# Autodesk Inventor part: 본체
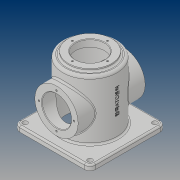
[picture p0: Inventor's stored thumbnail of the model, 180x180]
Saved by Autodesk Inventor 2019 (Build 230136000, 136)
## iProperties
Created: 2019-03
Part Number: 본체
Material: 일반
Document SubType Name: Modeling
Designer: PC312-19
Density: 1 g/cm^3
Appearance: 기본값
Author: PC312-19
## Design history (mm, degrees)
sketch "스케치1"
  geometry: C1 r 50 at (0, 0); 1 further point
  constraints: 1 centre point, 1 coincident
  dimensions: "d0" = 100 diameter of C1
extrude "돌출1" new body sketch "스케치1" stored distance "d1" = 120; taper "d2" = 0 deg
sketch "스케치2"
  geometry: C1 r 45 at (0, 0); 1 further point
  constraints: 1 centre point, 1 coincident
  dimensions: "d3" = 90 diameter of C1
extrude "돌출2" cut sketch "스케치2" distance "d4" = 112; taper "d5" = 0 deg
sketch "스케치3"
  geometry: C1 r 40 at (0, 0); 1 further point
  constraints: 1 centre point, 1 coincident
  dimensions: "d6" = 80 diameter of C1
extrude "돌출3" join sketch "스케치3" distance "d7" = 5; taper "d8" = 0 deg
sketch "스케치4"
  geometry: C1 r 27 at (0, 0); 1 further point
  constraints: 1 centre point, 1 coincident
  dimensions: "d9" = 54 diameter of C1
extrude "돌출4" cut sketch "스케치4" distance "d10" = 13; taper "d11" = 0 deg
node "작업 평면1"
sketch "스케치6"
  geometry: C1 r 40 at (0, 0); 1 further point
  constraints: 1 centre point, 1 coincident
  dimensions: "d13" = 80 diameter of C1
extrude "돌출5" join sketch "스케치6" stored distance "d14" = 13; taper "d15" = 0 deg
sketch "스케치7"
  geometry: 2 further points
  constraints: 1 vertical alignment
  dimensions: "d16" = 32.5 distance of point (0, 0) point (0, 32.5)
hole "구멍1" sketch "스케치7" at (0, 32.5) diameter "d17" = 3.242; stored, may be unused: countersink angle "d21" = 90 deg, drill point angle "d23" = 118 deg; dims "d18" = 8, "d19" = 4, "d20" = 2, "d22" = 10
sketch "스케치8"
  geometry: C1 r 27 at (0, 0); 1 further point
  constraints: 1 centre point, 1 coincident
  dimensions: "d27" = 54 diameter of C1
extrude "돌출6" cut sketch "스케치8" extent not by distance; stored distance "d28" = 13; taper "d29" = 0 deg
sketch "스케치9"
  geometry: L1 (70, 70)-(-70, 70); L2 (-70, 70)-(-70, -70); L3 (-70, -70)-(70, -70); L4 (70, -70)-(70, 70); L5 (70, 70)-(-70, -70); L6 (-70, 70)-(70, -70); C1 r 50 at (0, 0) reference; C2 r 45 at (0, 0) reference; 1 further point
  constraints: 12 end point, 2 midpoint, 2 parallel, 1 horizontal, 1 perpendicular
  dimensions: "d30" = 140 distance of L3.end L2.end; "d31" = 140 distance of L2.end L1.end
extrude "돌출7" join sketch "스케치9" distance "d32" = 10; taper "d33" = 0 deg
fillet "모깎기1" dims "d34" = 10
sketch "스케치10"
  geometry: C1 r 4.5 at (60, -60); C2 r 4.5 at (-60, -60); C3 r 4.5 at (-60, 60); C4 r 4.5 at (60, 60); 13 further points
  constraints: 4 centre point, 4 coincident, 4 other
  dimensions: "d35" = 9 diameter of C1; "d36" = 9 diameter of C2; "d37" = 9 diameter of C3; "d38" = 9 diameter of C4
extrude "돌출8" cut sketch "스케치10" extent not by distance; stored distance "d39" = 10; taper "d40" = 0 deg
node "작업 평면2"
sketch "스케치11"
  geometry: L1 (-50, 60)-(-50, -60) reference; L2 (-60, -60)-(-60, 60) reference; 2 further points
  constraints: 1 horizontal alignment, 1 other
  dimensions: "d65" = 70 distance from line of L2 point (10, 0)
feature "엠보싱1" sketch "스케치11" dims "d12" = 62, "d43" = 0.5, "d44" = 0
fillet "모깎기2" dims "d45" = 3
fillet "모깎기3" dims "d46" = 5
fillet "모깎기4" dims "d47" = 3
chamfer "모따기1" distance "d48" = 1; stored, may be unused: second distance "d49" = 2, angle "d50" = 45 deg
sketch "스케치12"
  geometry: 2 further points
  constraints: 1 vertical alignment
  dimensions: "d52" = 32.5 distance of point (0, 0) point (0, 32.5)
hole "구멍2" sketch "스케치12" at (0, 32.5) diameter "d53" = 3.242; stored, may be unused: countersink angle "d57" = 90 deg, drill point angle "d59" = 118 deg; dims "d54" = 8, "d55" = 4, "d56" = 2, "d58" = 10
fillet "모깎기6" dims "d63" = 3
fillet "모깎기7" dims "d64" = 3
node "솔리드1"
pattern_circular "원형 패턴1" dims angle "d25" = 360 deg
mirror "미러1"
pattern_circular "원형 패턴2" dims angle "d61" = 360 deg
other parameters: "d41" = 95.5
